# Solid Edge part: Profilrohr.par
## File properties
Dokumentum tartalom típus: 0
Last saved by: ahadarics
Revision: 76
Sűrűség: 0,000 kg/m^3
Pontosság: 0,990
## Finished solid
Body 1: solid body, 6 faces, 6 edges, 0 vertices.
  Faces by surface: cone 2, cylinder 2, plane 2
  Edges by curve: circle 6
Bounding box of the edges (mm): 65.400 x 65.400 x 82.000, from (-32.7, -32.7, -41) to (32.7, 32.7, 41).
Cylindrical faces by radius (mm): R31.5 x1, R32.7 x1
Conical faces (half-angle, radius in mm at the cone's reference point): 15 deg R31.567 x2
Planar faces by outward normal: +z 1, -z 1
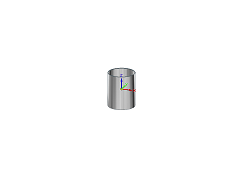
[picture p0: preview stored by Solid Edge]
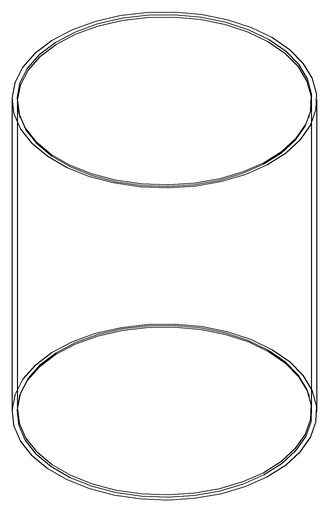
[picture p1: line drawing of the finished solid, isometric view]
